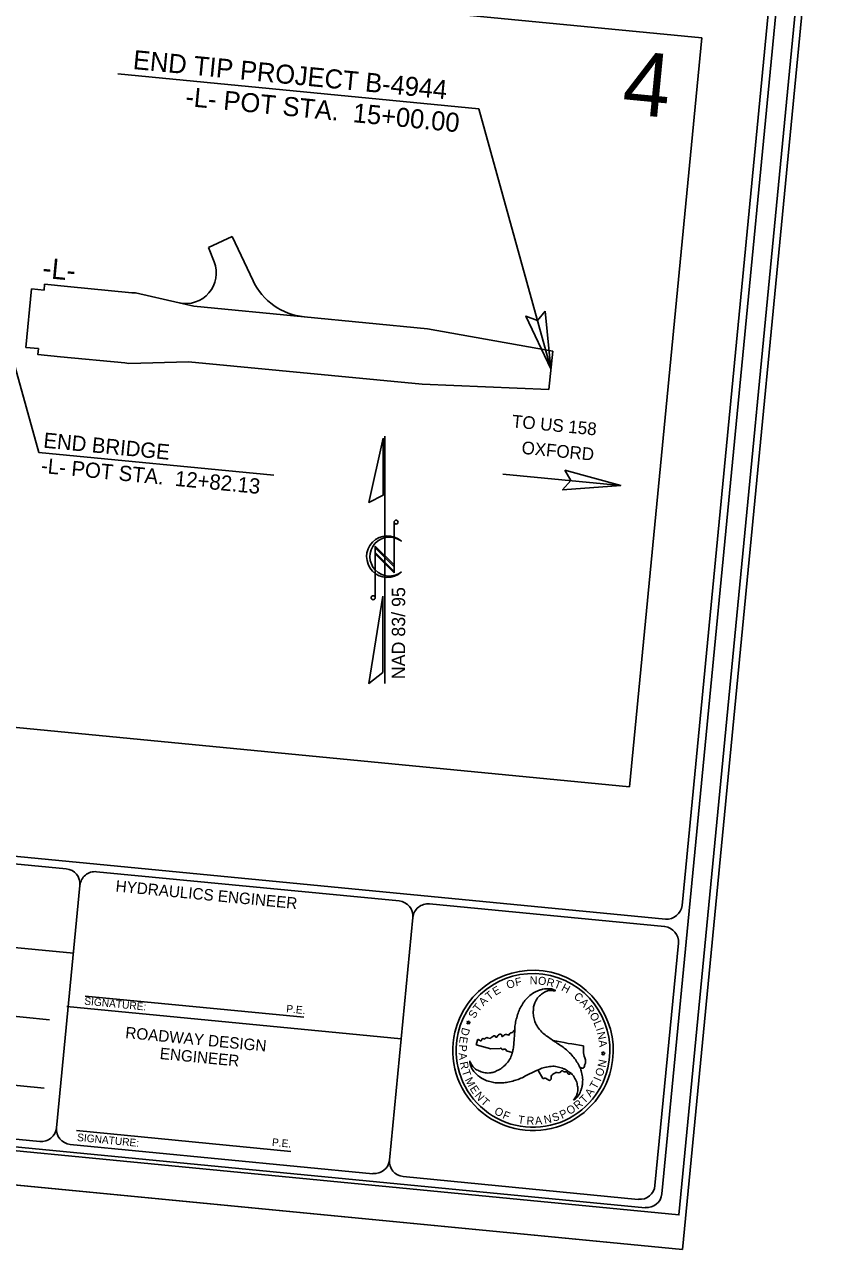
# Model space of a CAD drawing. Extents: x 2060574 to 2063008, y 912203 to 913082.
# Drawn here: x 2061320.5 to 2061643.3, y 912328.1 to 912811 of the extents above; entities that cross this region are included whole.
import ezdxf

# ---------------------------------------------------------------- set-up
doc = ezdxf.new("R2010")
doc.units = 0
for name, color, linetype in [('Prop Shade Medium', 7, 'Continuous'), ('Prop Terminator CELL', 7, 'Continuous'), ('Sheet Cutting Line CELL', 7, 'Continuous'), ('Sheet Data Field CELL', 7, 'Continuous'), ('Sheet North Arrow CELL', 7, 'Continuous'), ('Sheet Plot Border Inside CELL', 7, 'Continuous'), ('Sheet Plot Border Outside CELL', 7, 'Continuous'), ('Sheet Title CELL', 7, 'Continuous')]:
    doc.layers.add(name, color=color, linetype=linetype)

msp = doc.modelspace()

# ---------------------------------------------------------------- linework, layer by layer
at = {"layer": 'Prop Shade Medium'}
for p, q in [((2061402.29, 912727.44), (2061393.02, 912723.05)), ((2061410.58, 912709.94), (2061402.29, 912727.44)), ((2061393.02, 912723.05), (2061395.26, 912717.37)), ((2061323.22, 912706.74), (2061320.99, 912683.68)), ((2061381.46, 912701.27), (2061387.27, 912699.96)), ((2061387.27, 912699.96), (2061430.77, 912695.76)), ((2061528.68, 912682.25), (2061479.3, 912691.07)), ((2061527.21, 912667.04), (2061528.68, 912682.25)), ((2061385.15, 912678.07), (2061477.19, 912669.17)), ((2061477.19, 912669.17), (2061527.21, 912667.04))]:
    msp.add_line(p, q, dxfattribs=at)
for points in [[(2061387.27, 912699.96), (2061381.46, 912701.27), (2061381.46, 912701.27), (2061364.22, 912705.14), (2061362.76, 912705.26), (2061337.38, 912707.72), (2061328.42, 912708.58), (2061328.19, 912706.26), (2061323.22, 912706.74)], [(2061479.3, 912691.07), (2061430.77, 912695.76), (2061430.77, 912695.76), (2061387.27, 912699.96)], [(2061320.99, 912683.68), (2061325.96, 912683.2), (2061325.74, 912680.88), (2061334.7, 912680.01), (2061360.08, 912677.56), (2061361.54, 912677.41), (2061385.15, 912678.07)]]:
    msp.add_lwpolyline(points, dxfattribs=at)
for centre, radius, start, end in [((2061384.09, 912712.98), 12, 257.3547, 21.4729), ((2061433.17, 912720.64), 25, 205.3407, 264.4786)]:
    msp.add_arc(centre, radius, start, end, dxfattribs=at)
at = {"layer": 'Prop Terminator CELL'}
for points in [[(2061525.73, 912698.03), (2061528.01, 912675.31), (2061518.11, 912696.04), (2061522.73, 912694.34)], [(2061533.47, 912635.33), (2061555.49, 912629.31), (2061532.59, 912627.5), (2061535.83, 912631.21)]]:
    msp.add_lwpolyline(points, close=True, dxfattribs=at)
at = {"layer": 'Sheet Cutting Line CELL'}
msp.add_line((2060574.1, 912425.31), (2061579.81, 912328.1), dxfattribs=at)
at = {"layer": 'Sheet Data Field CELL'}
for p, q in [((2061357.31, 912791.5), (2061499.6, 912777.74)), ((2061499.6, 912777.74), (2061528.01, 912675.31)), ((2061311.15, 912696.27), (2061326.15, 912642.22)), ((2061326.15, 912642.22), (2061418.77, 912633.27)), ((2061509.08, 912633.79), (2061555.49, 912629.31))]:
    msp.add_line(p, q, dxfattribs=at)
msp.add_lwpolyline([(2061010.39, 912861.5), (2061587.46, 912805.72), (2061558.93, 912510.54), (2060981.86, 912566.32)], close=True, dxfattribs=at)
at = {"layer": 'Sheet North Arrow CELL'}
for p, q in [((2061462.5, 912551.26), (2061462.5, 912648.76)), ((2061466.17, 912614.83), (2061466.17, 912594.82)), ((2061468.93, 912607.38), (2061469.04, 912607.3)), ((2061466.17, 912597.94), (2061458.72, 912605.4)), ((2061458.72, 912605.4), (2061458.72, 912585.06)), ((2061466.17, 912597.21), (2061458.72, 912604.66)), ((2061458.72, 912604.66), (2061458.72, 912602.83)), ((2061466.17, 912595.38), (2061458.72, 912602.83)), ((2061458.72, 912602.83), (2061466.17, 912595.38)), ((2061466.17, 912594.82), (2061458.72, 912602.28)), ((2061466.17, 912595.38), (2061466.17, 912597.21))]:
    msp.add_line(p, q, dxfattribs=at)
for points in [[(2061461.82, 912647.91), (2061456.26, 912622.59), (2061461.82, 912625.41)], [(2061461.7, 912585.61), (2061456.18, 912551.26), (2061461.7, 912555.61)]]:
    msp.add_lwpolyline(points, close=True, dxfattribs=at)
for centre in [(2061466.97, 912614.82), (2061457.92, 912585.03)]:
    msp.add_circle(centre, 0.795, dxfattribs=at)
for centre, radius, start, end in [((2061463.53, 912601.23), 8.19, 47.84, 312.3941), ((2061464.33, 912601.24), 7.68, 53.095, 308.6287)]:
    msp.add_arc(centre, radius, start, end, dxfattribs=at)
at = {"layer": 'Sheet Plot Border Inside CELL'}
msp.add_lwpolyline([(2060583.16, 912437.96), (2061578.42, 912341.76), (2061639.33, 912971.88), (2060644.07, 913068.09)], close=True, dxfattribs=at)
at = {"layer": 'Sheet Plot Border Outside CELL'}
msp.add_lwpolyline([(2061643.31, 912985.03), (2060637.6, 913082.24), (2060574.1, 912425.31), (2061579.81, 912328.1)], close=True, dxfattribs=at)
at = {"layer": 'Sheet Title CELL'}
for p, q in [((2060725.07, 912540.32), (2061573.11, 912458.35)), ((2061166.72, 912494.62), (2061336.92, 912478.16)), ((2061348.87, 912477.01), (2061468.17, 912465.48)), ((2061333.08, 912376.05), (2061342.32, 912471.61)), ((2061339.73, 912444.88), (2061157.58, 912462.5)), ((2061480.12, 912464.32), (2061572.82, 912455.36)), ((2061464.33, 912363.37), (2061473.57, 912458.93)), ((2061237.67, 912427.63), (2061330.33, 912418.66)), ((2061344.43, 912428.01), (2061430.58, 912419.69)), ((2061529.87, 912430.21), (2061529.8, 912430.16)), ((2061529.87, 912430.21), (2061529.8, 912430.16)), ((2061337.16, 912423.9), (2061468.95, 912411.16)), ((2061495.18, 912417.53), (2061494.82, 912417.95)), ((2061494.82, 912417.95), (2061495.36, 912417.83)), ((2061494.9, 912417.06), (2061495.18, 912417.53)), ((2061495.36, 912417.83), (2061495.62, 912418.29)), ((2061495.62, 912418.29), (2061495.69, 912417.75)), ((2061495.69, 912417.75), (2061496.22, 912417.63)), ((2061496.22, 912417.63), (2061495.71, 912417.41)), ((2061495.39, 912417.28), (2061494.9, 912417.06)), ((2061495.75, 912416.86), (2061495.39, 912417.28)), ((2061495.71, 912417.41), (2061495.75, 912416.86)), ((2061498.54, 912408.72), (2061499.04, 912410.56)), ((2061504.34, 912407.14), (2061498.54, 912408.72)), ((2061528.77, 912410.53), (2061528.77, 912410.53)), ((2061507.92, 912407.35), (2061504.34, 912407.14)), ((2061512.84, 912405.77), (2061510.4, 912406.37)), ((2061548.47, 912405.65), (2061547.94, 912405.78)), ((2061547.94, 912405.78), (2061548.31, 912405.36)), ((2061548.31, 912405.36), (2061548.03, 912404.89)), ((2061548.03, 912404.89), (2061548.52, 912405.1)), ((2061548.75, 912406.11), (2061548.47, 912405.65)), ((2061548.52, 912405.1), (2061548.87, 912404.69)), ((2061548.82, 912405.57), (2061548.75, 912406.11)), ((2061549.34, 912405.47), (2061548.82, 912405.57)), ((2061548.84, 912405.24), (2061549.34, 912405.47)), ((2061548.87, 912404.69), (2061548.84, 912405.24)), ((2061234.86, 912400.77), (2061328.18, 912391.75)), ((2061524.8, 912395.45), (2061522.86, 912398.86)), ((2061522.86, 912398.86), (2061522.86, 912398.86)), ((2061551.73, 912399.41), (2061551.73, 912399.41)), ((2061340.96, 912374.97), (2061425.47, 912366.79))]:
    msp.add_line(p, q, dxfattribs=at)
for points in [[(2061571.68, 912349.98), (2061631.14, 912965.11)], [(2061579.66, 912463.73), (2061627.87, 912962.42)], [(2061568.98, 912353.26), (2061578.22, 912448.81)], [(2060681.25, 912430.02), (2061565.13, 912344.58)], [(2061156.33, 912387.12), (2061326.53, 912370.66)], [(2061338.48, 912369.51), (2061457.79, 912357.98)], [(2061469.73, 912356.82), (2061562.43, 912347.86)]]:
    msp.add_lwpolyline(points, dxfattribs=at)
for centre, radius, start, end in [((2061336.35, 912472.22), 6, 354.4787, 84.4787), ((2061348.3, 912471.06), 6, 84.4787, 174.4787), ((2061467.6, 912459.5), 6, 354.4787, 84.4787), ((2061479.54, 912458.35), 6, 84.4787, 174.4787), ((2061573.7, 912464.34), 6, 264.4787, 354.4787), ((2061572.25, 912449.41), 6, 354.4787, 84.4787), ((2061520.93, 912406.57), 31.63, 346.8998, 166.8998), ((2061520.93, 912406.57), 30.31, 346.8998, 166.8998), ((2061520.93, 912406.57), 31.63, 166.8998, 346.8998), ((2061520.93, 912406.57), 30.31, 166.8998, 346.8998), ((2061563.39, 912573.66), 166.77, 252.5783, 252.6779), ((2061563.39, 912573.66), 166.77, 258.0174, 262.2234), ((2061327.11, 912376.66), 6, 264.4787, 354.4787), ((2061339.06, 912375.51), 6, 174.4787, 264.4787), ((2061458.37, 912363.98), 6, 264.4787, 354.4787), ((2061470.31, 912362.83), 6, 174.4787, 264.4787), ((2061563.02, 912353.86), 6, 264.4787, 354.4787), ((2061565.71, 912350.58), 6, 264.4787, 354.4787)]:
    msp.add_arc(centre, radius, start, end, dxfattribs=at)
for points in [[(2061529.8, 912430.16), (2061529.15, 912430.51), (2061527.09, 912430.9), (2061524.85, 912430.72), (2061524.64, 912430.66), (2061523.47, 912430.35), (2061522.18, 912429.79), (2061520.14, 912428.6), (2061518.41, 912426.95), (2061517.7, 912426.24), (2061517.09, 912425.3), (2061515.9, 912423.29), (2061515.06, 912421.27), (2061514.35, 912418.85), (2061513.88, 912416.68), (2061513.73, 912414.4), (2061513.59, 912412.09), (2061513.41, 912409.86), (2061513.2, 912407.57), (2061512.69, 912405.37), (2061512.64, 912405.18), (2061511.7, 912402.93), (2061510.27, 912401.09), (2061508.65, 912399.65), (2061507.74, 912399.03), (2061506.52, 912398.46), (2061505.83, 912398.13), (2061504.27, 912397.75), (2061502.04, 912397.74), (2061500.01, 912398.34), (2061498.29, 912399.23), (2061496.92, 912400.64), (2061496, 912402.41)], [(2061536.95, 912387.02), (2061537.54, 912387.4), (2061538.93, 912389), (2061539.9, 912391.02), (2061539.97, 912391.23), (2061540.27, 912392.4), (2061540.43, 912393.82), (2061540.44, 912396.17), (2061539.85, 912398.48), (2061539.61, 912399.46), (2061539.09, 912400.47), (2061537.95, 912402.5), (2061536.63, 912404.24), (2061534.88, 912406.05), (2061533.23, 912407.52), (2061531.33, 912408.83), (2061529.4, 912410.09), (2061527.58, 912411.35), (2061525.67, 912412.7), (2061524.03, 912414.23), (2061523.91, 912414.38), (2061522.4, 912416.33), (2061521.53, 912418.49), (2061521.08, 912420.6), (2061521.02, 912421.68), (2061521.14, 912423.03), (2061521.18, 912423.81), (2061521.65, 912425.34), (2061522.76, 912427.29), (2061524.28, 912428.73), (2061525.92, 912429.77), (2061527.83, 912430.25), (2061529.8, 912430.16), (2061529.87, 912430.21)], [(2061499.04, 912410.56), (2061499.02, 912410.75), (2061499.37, 912410.88), (2061500.16, 912410.32), (2061500.68, 912410.59), (2061500.75, 912410.97), (2061501.19, 912411.26), (2061501.75, 912411.01), (2061502.45, 912411.57), (2061502.97, 912411.57), (2061504.01, 912411.33), (2061505.53, 912412.28), (2061506.07, 912412.24), (2061506.12, 912411.88), (2061506.43, 912411.74), (2061507.2, 912412.64), (2061507.37, 912412.75), (2061508.42, 912412.91), (2061508.64, 912412.67), (2061508.6, 912412.2), (2061508.72, 912412.07), (2061509.09, 912412.23), (2061509.65, 912412.67), (2061510.54, 912412.9), (2061511.42, 912412.58), (2061511.74, 912413.28), (2061512.97, 912413.75), (2061513.29, 912414.13), (2061513.44, 912414.55)], [(2061513.73, 912414.46), (2061513.73, 912414.4), (2061513.59, 912412.09), (2061513.41, 912409.86), (2061513.2, 912407.57), (2061512.83, 912405.77)], [(2061539.46, 912399.84), (2061539.09, 912400.47), (2061537.95, 912402.5), (2061536.63, 912404.24), (2061534.88, 912406.05), (2061533.23, 912407.52), (2061531.33, 912408.83), (2061529.4, 912410.09), (2061528.77, 912410.53)], [(2061540.82, 912408.42), (2061540.78, 912406.27), (2061541.29, 912403.6), (2061541.68, 912402.11), (2061541.39, 912400.97), (2061540.81, 912399.68), (2061539.47, 912399.84)], [(2061510.4, 912406.37), (2061510.27, 912406.87), (2061509.83, 912407.12), (2061509.11, 912406.93), (2061508.63, 912407.07), (2061508.19, 912407.57), (2061507.92, 912407.35)], [(2061496, 912402.41), (2061496.06, 912401.67), (2061496.74, 912399.68), (2061498, 912397.83), (2061498.15, 912397.7), (2061499.02, 912396.81), (2061500.15, 912395.99), (2061502.21, 912394.8), (2061504.48, 912394.15), (2061505.45, 912393.88), (2061506.62, 912393.82), (2061508.91, 912393.81), (2061511.06, 912394.07), (2061513.54, 912394.67), (2061515.62, 912395.35), (2061517.7, 912396.36), (2061519.76, 912397.41), (2061521.78, 912398.36), (2061523.88, 912399.3), (2061526.03, 912399.99), (2061526.26, 912400.02), (2061528.69, 912400.34), (2061530.96, 912400.02), (2061533, 912399.36), (2061534.03, 912398.88), (2061535.09, 912398.08), (2061535.77, 912397.66), (2061536.86, 912396.5), (2061537.96, 912394.57), (2061538.47, 912392.53), (2061538.55, 912390.58), (2061538.02, 912388.69), (2061536.95, 912387.02)], [(2061522.86, 912398.86), (2061523.88, 912399.3), (2061526.03, 912399.99), (2061526.26, 912400.02), (2061528.69, 912400.34), (2061530.96, 912400.02), (2061533, 912399.36), (2061534.03, 912398.88), (2061535.09, 912398.08), (2061535.72, 912397.68)], [(2061535.71, 912397.68), (2061535.3, 912397.2), (2061534.83, 912397.28), (2061534.16, 912398.11), (2061533.12, 912398.14), (2061532.73, 912398.52), (2061532.43, 912398.59), (2061531.5, 912397.86), (2061530.46, 912397.87), (2061528.59, 912397.06), (2061528.1, 912396.45), (2061527.87, 912394.95), (2061527.41, 912394.75), (2061526.96, 912394.93), (2061526.06, 912395.54), (2061524.8, 912395.45)]]:
    msp.add_spline(points, degree=3, dxfattribs=at)

# ---------------------------------------------------------------- texts
at = {"layer": 'Sheet Data Field CELL'}
for s, height, p in [('END TIP PROJECT B-4944', 7.5, (2061363, 912793.46)), ('4', 25, (2061555.53, 912775.95)), ('-L- POT STA.  15+00.00', 7.5, (2061383.66, 912778.9)), ('-L-', 8, (2061327.29, 912711.16)), ('TO US 158', 5, (2061512.47, 912652.19)), ('END BRIDGE', 6, (2061327.74, 912644.2)), ('OXFORD', 5, (2061516.26, 912641.78)), ('-L- POT STA.  12+82.13', 6, (2061326.77, 912634.25))]:
    msp.add_text(s, height=height, rotation=354.4787, dxfattribs=at).set_placement(p)
at = {"layer": 'Sheet North Arrow CELL'}
msp.add_text('NAD 83/ 95', height=5.25, rotation=90, dxfattribs=at).set_placement((2061470.52, 912552.9))
at = {"layer": 'Sheet Title CELL'}
for s, height, rotation, p in [(' HYDRAULICS ENGINEER', 4.5, 354.4787, (2061354.58, 912469.37)), ('E', 3.14, 31.0568, (2061506.11, 912428.1)), ('O', 3.16, 19.1174, (2061511.04, 912430.74)), ('F', 3.16, 11.9706, (2061514.2, 912431.82)), ('N', 3.15, 359.8836, (2061519.62, 912432.66)), ('O', 3.16, 352.3855, (2061522.71, 912432.64)), ('R', 3.15, 345.7756, (2061526.01, 912432.2)), ('T', 3.16, 339.1259, (2061528.94, 912431.46)), ('H', 3.15, 332.0412, (2061531.82, 912430.34)), ('SIGNATURE:', 3, 354.4787, (2061343.94, 912424.63)), ('A', 3.16, 45.2276, (2061501.38, 912423.89)), ('T', 3.15, 38.1724, (2061503.68, 912426.2)), ('C', 3.14, 319.6989, (2061536.72, 912427.41)), ('P.E.', 3, 354.4787, (2061423.55, 912421.6)), ('S', 3.15, 58.6561, (2061497.89, 912418.91)), ('T', 3.16, 52.2799, (2061499.46, 912421.47)), ('A', 3.15, 312.2018, (2061539.11, 912425.36)), ('R', 3.15, 305.8379, (2061541.29, 912422.97)), ('O', 3.16, 298.7183, (2061543.04, 912420.52)), ('L', 3.15, 292.4846, (2061544.66, 912417.57)), ('ROADWAY DESIGN', 4.4996, 354.4787, (2061360.07, 912411.46)), ('D', 3.15, 254.7528, (2061493.12, 912415.79)), ('I', 3.16, 288.4953, (2061545.65, 912415.03)), ('N', 3.15, 282.7952, (2061546.11, 912413.56)), ('P', 3.15, 268.5731, (2061491.73, 912408.89)), ('E', 3.14, 261.0407, (2061492.2, 912412.29)), ('A', 3.15, 275.3632, (2061546.78, 912410.54)), ('ENGINEER', 4.5, 354.4787, (2061373.65, 912403.21)), ('A', 3.15, 275.1657, (2061491.65, 912405.52)), ('R', 3.15, 282.2343, (2061492.03, 912401.81)), ('T', 3.15, 288.8849, (2061492.8, 912398.41)), ('O', 3.14, 71.8599, (2061548.28, 912396.04)), ('N', 3.15, 79.108, (2061549.44, 912399.67)), ('M', 3.15, 296.1199, (2061494, 912395.04)), ('T', 3.15, 61.0744, (2061545.79, 912391.05)), ('I', 3.16, 66.7243, (2061547.5, 912394.17)), ('E', 3.15, 303.5867, (2061495.83, 912391.47)), ('N', 3.16, 310.5582, (2061497.74, 912388.66)), ('T', 3.14, 45.9029, (2061541.19, 912385.39)), ('A', 3.16, 53.99, (2061543.63, 912388)), ('T', 3.15, 317.4002, (2061500.09, 912385.98)), ('O', 3.15, 330.7039, (2061505.33, 912381.76)), ('O', 3.16, 32.6141, (2061535.33, 912381.05)), ('R', 3.16, 39.8032, (2061538.53, 912383.12)), ('F', 3.15, 337.8691, (2061508.68, 912379.94)), ('T', 3.14, 350.7784, (2061514.8, 912377.9)), ('R', 3.16, 357.735, (2061518.33, 912377.37)), ('A', 3.14, 4.4881, (2061521.82, 912377.28)), ('N', 3.14, 11.5197, (2061525.53, 912377.63)), ('S', 3.14, 18.7302, (2061529.01, 912378.41)), ('P', 3.15, 25.9221, (2061532.31, 912379.55)), ('SIGNATURE:', 3, 354.4787, (2061341.11, 912370.91)), ('P.E.', 3, 354.4787, (2061417.93, 912368.97))]:
    msp.add_text(s, height=height, rotation=rotation, dxfattribs=at).set_placement(p)

doc.saveas('drawing.dxf')
